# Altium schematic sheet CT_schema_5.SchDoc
size 301 x 177 mm
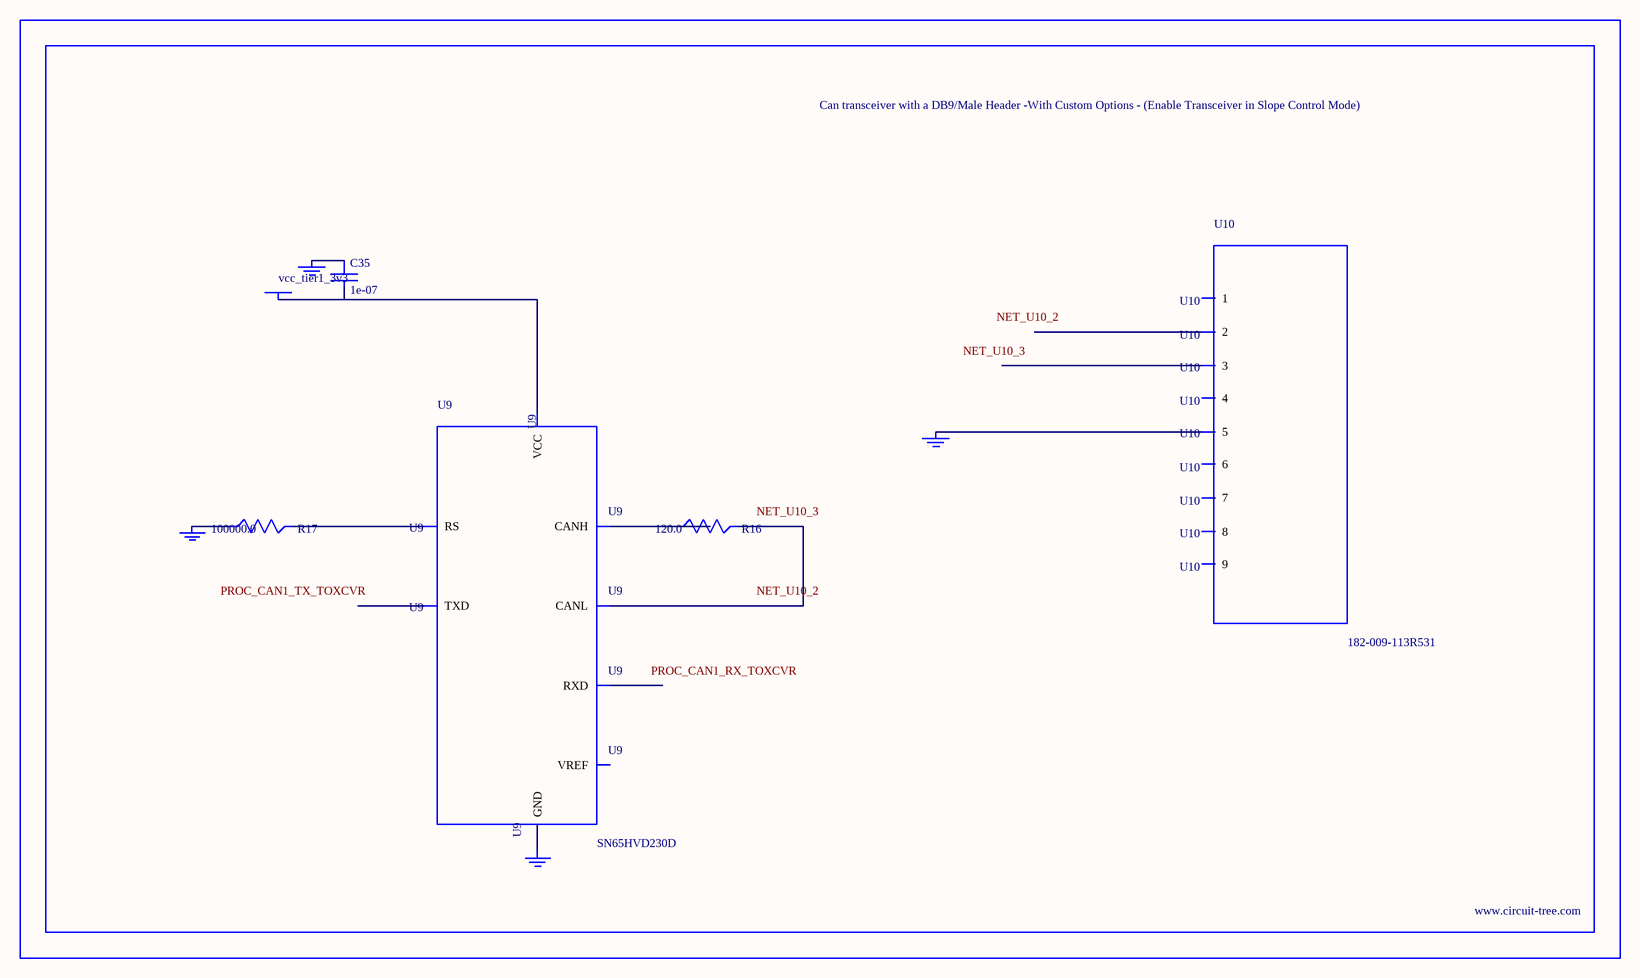
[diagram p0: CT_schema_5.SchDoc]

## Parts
BORDER4  (no value)
C35  1e-07  [C0402]
GND_INSTANCE_4_0  (no value)
GND_INSTANCE_4_1  (no value)
GND_INSTANCE_4_2  (no value)
GND_INSTANCE_4_3  (no value)
POWER_INSTANCE_4_0  vcc_tier1_3v3
R16  120.0  [R0603]
R17  100000.0  [R0603]
U9  SN65HVD230D  [SOIC-8]
U10  182-009-113R531  [182-009-MALE]

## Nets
NetC35_1: C35.1 GND_INSTANCE_4_0.0(GND)
NetC35_2: C35.2 POWER_INSTANCE_4_0.0(PWR) U9.3(VCC)
NetGND_INSTANCE_4_1_0: GND_INSTANCE_4_1.0(GND) R17.1
NetGND_INSTANCE_4_2_0: GND_INSTANCE_4_2.0(GND) U9.2(GND)
NetGND_INSTANCE_4_3_0: GND_INSTANCE_4_3.0(GND) U10.5
NetR16_1: R16.1 U9.7(CANH)
NetR16_2: R16.2 U9.6(CANL)
NetR17_2: R17.2 U9.8(RS)

Not connected (* = marked no-connect by the designer): U9 1(TXD) 4(RXD) 5(VREF); U10 1 2 3 4 6 7 8 9

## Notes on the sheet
- Labels drawn without touching a wire or pin: NET_U10_2, NET_U10_3, PROC_CAN1_RX_TOXCVR, PROC_CAN1_TX_TOXCVR

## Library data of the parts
BORDER4 = BORDER_PAGE4
C35 = C0402C104K3RACTU
GND_INSTANCE_4_0-GND_INSTANCE_4_3 = GND
POWER_INSTANCE_4_0 = PWR
R16 = RC0603JR-07120RL
R17 = RC0603JR-07100KL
